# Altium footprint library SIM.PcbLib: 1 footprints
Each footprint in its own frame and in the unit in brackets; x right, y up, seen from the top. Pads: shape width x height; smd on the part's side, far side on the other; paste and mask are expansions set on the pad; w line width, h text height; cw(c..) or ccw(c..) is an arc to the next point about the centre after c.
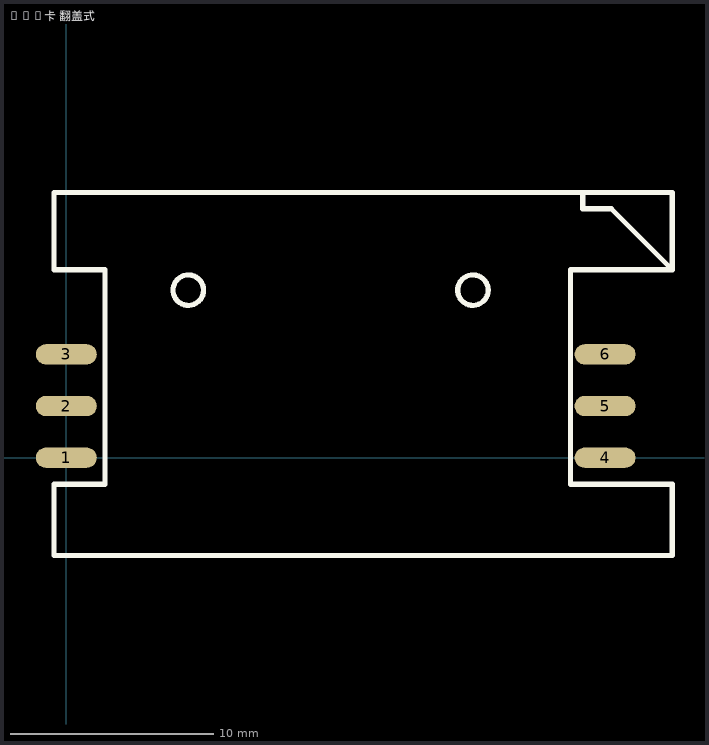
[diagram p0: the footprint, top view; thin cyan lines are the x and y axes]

## SIM卡 翻盖式 [mm]
pads (6):
  oval 3x1 smd: 1(0,0) 2(0,2.54) 3(0,5.08) 4(26.5,0) 5(26.5,2.54) 6(26.5,5.08)
Top Overlay:
  circle w0.254: c6,8.24 r0.75
  circle w0.254: c20,8.24 r0.75
  lines w0.254: 25.4,13.04 25.4,12.24 26.8,12.24 29.8,9.24 ; 29.8,9.24 29.8,13.04 24.049,13.04 -0.6,13.04 -0.6,9.24 1.9,9.24 1.9,-1.31 -0.6,-1.31 -0.6,-4.81 29.8,-4.81 29.8,-1.31 24.8,-1.31 24.8,9.24 29.8,9.24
